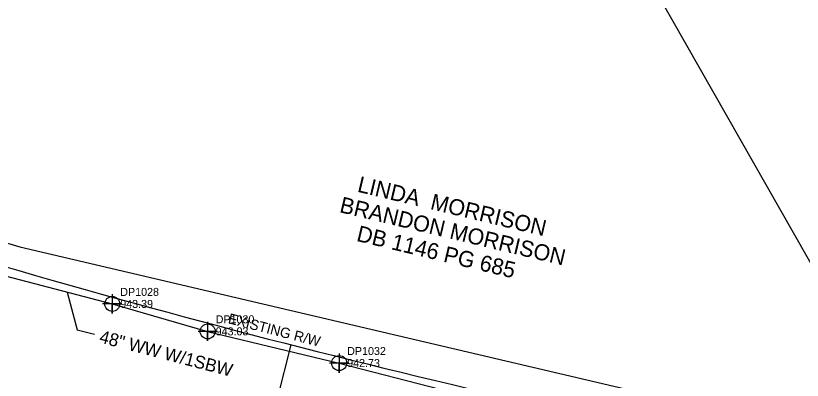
# Model space of a CAD drawing. Extents: x 1182322 to 1186765, y 572295 to 575411.
# Drawn here: x 1185597.5 to 1185843, y 573907.5 to 574021.2 of the extents above; entities that cross this region are included whole.
import ezdxf

# ---------------------------------------------------------------- set-up
doc = ezdxf.new("R2010")
doc.units = 0
for name, color, linetype in [('COGO Default Chain', 7, 'Continuous'), ('Exist Guardrail', 7, 'Continuous'), ('Exist Horizontal Alignment', 7, 'Continuous'), ('Exist Other Culture Fence Line', 7, 'Continuous'), ('Exist Other Culture Fence Line Cogo Elevation', 7, 'Continuous'), ('Exist Other Culture Fence Line Cogo Number', 7, 'Continuous'), ('Exist Other Culture Fence Line Cogo Point CELL', 7, 'Continuous'), ('Exist Other Culture Fence Line Leader', 7, 'Continuous'), ('Exist Other Culture Fence Line Text', 7, 'Continuous'), ('Exist Property Deed Book Text', 7, 'Continuous'), ('Exist Property Line', 7, 'Continuous'), ('Exist Property Owner Text', 7, 'Continuous'), ('Exist Right of Way Line', 7, 'Continuous'), ('Exist Right of Way Line Text', 7, 'Continuous'), ('Exist Right of Way Width CELL', 7, 'Continuous'), ('Sheet Layout Plan Border', 7, 'Continuous')]:
    doc.layers.add(name, color=color, linetype=linetype)

msp = doc.modelspace()

# ---------------------------------------------------------------- linework, layer by layer
at = {"layer": 'COGO Default Chain'}
msp.add_arc((1186394.82, 576698.6), 2957.6, 249.39538, 256.24258, dxfattribs=at)
at = {"layer": 'Exist Guardrail'}
msp.add_spline([(1185390.3, 573940.07), (1185437.01, 573922.28), (1185484.33, 573906.54), (1185526.22, 573893.43), (1185574.13, 573879.46), (1185622.33, 573866.54), (1185670.88, 573853.88), (1185719.13, 573841.46), (1185767.43, 573829.33), (1185816.18, 573817.9), (1185864.94, 573807.26), (1185913.93, 573797.57), (1185963.25, 573788.74), (1186012.41, 573780.34), (1186049.41, 573774.82)], degree=3, dxfattribs=at)
at = {"layer": 'Exist Horizontal Alignment'}
msp.add_arc((1186394.82, 576698.6), 2957.6, 249.39538, 256.24258, dxfattribs=at)
at = {"layer": 'Exist Other Culture Fence Line'}
msp.add_lwpolyline([(1185576.16, 573944.72), (1185627.61, 573931.32), (1185657.39, 573922.77), (1185698.44, 573912.89), (1185744.14, 573901.13), (1185780.46, 573894.53), (1185823.78, 573885.57), (1185871, 573875.87), (1185917.72, 573864.77), (1185990.6, 573852.56)], dxfattribs=at)
at = {"layer": 'Exist Other Culture Fence Line Cogo Point CELL'}
for points in [[(1185627.61, 573934.32), (1185627.61, 573928.32), (1185627.61, 573931.32), (1185630.61, 573931.32), (1185624.61, 573931.32)], [(1185657.39, 573925.77), (1185657.39, 573919.77), (1185657.39, 573922.77), (1185660.39, 573922.77), (1185654.39, 573922.77)], [(1185698.44, 573915.89), (1185698.44, 573909.89), (1185698.44, 573912.89), (1185701.44, 573912.89), (1185695.44, 573912.89)]]:
    msp.add_lwpolyline(points, dxfattribs=at)
for centre in [(1185627.61, 573931.32), (1185657.39, 573922.77), (1185698.44, 573912.89)]:
    msp.add_circle(centre, 2.34, dxfattribs=at)
at = {"layer": 'Exist Other Culture Fence Line Leader'}
msp.add_lwpolyline([(1185613.58, 573934.98), (1185616.67, 573923.27), (1185622.09, 573921.86)], dxfattribs=at)
at = {"layer": 'Exist Property Line'}
msp.add_line((1185885.38, 573874.21), (1185478.65, 574588.33), dxfattribs=at)
at = {"layer": 'Exist Right of Way Line'}
for centre, radius, start, end in [((1186394.82, 576698.6), 2869.6, 249.39538, 256.24258), ((1186442.72, 576894.22), 3071, 256.24258, 262.82154)]:
    msp.add_arc(centre, radius, start, end, dxfattribs=at)
at = {"layer": 'Exist Right of Way Width CELL'}
msp.add_line((1185683.4, 573918.58), (1185674.31, 573883.06), dxfattribs=at)
at = {"layer": 'Sheet Layout Plan Border'}
for p, q in [((1185573.26, 573956.52), (1185598.72, 573949.14)), ((1185598.72, 573949.14), (1185890.83, 573880.78))]:
    msp.add_line(p, q, dxfattribs=at)

# ---------------------------------------------------------------- texts
at = {"layer": 'Exist Other Culture Fence Line Cogo Elevation'}
for s, p in [('943.39', (1185630.11, 573930.07)), ('943.03', (1185659.89, 573921.52)), ('942.73', (1185700.94, 573911.64))]:
    msp.add_text(s, height=2.5, dxfattribs=at).set_placement(p)
at = {"layer": 'Exist Other Culture Fence Line Cogo Number'}
for s, p in [('DP1028', (1185630.11, 573933.82)), ('DP1030', (1185659.89, 573925.27)), ('DP1032', (1185700.94, 573915.39))]:
    msp.add_text(s, height=2.5, dxfattribs=at).set_placement(p)
at = {"layer": 'Exist Other Culture Fence Line Text'}
msp.add_text('48" WW W/1SBW', height=4, rotation=345.4063, dxfattribs=at).set_placement((1185623.32, 573919.35))
at = {"layer": 'Exist Property Deed Book Text'}
msp.add_text('DB 1146 PG 685', height=5, rotation=346.605, dxfattribs=at).set_placement((1185703.6, 573951))
at = {"layer": 'Exist Property Owner Text'}
for s, p in [('LINDA  MORRISON', (1185703.86, 573966.35)), ('BRANDON MORRISON', (1185698.29, 573959.97))]:
    msp.add_text(s, height=5, rotation=346.605, dxfattribs=at).set_placement(p)
at = {"layer": 'Exist Right of Way Line Text'}
msp.add_text('EXISTING R/W', height=3.2, rotation=345.5456, dxfattribs=at).set_placement((1185663.54, 573925.35))

doc.saveas('drawing.dxf')
